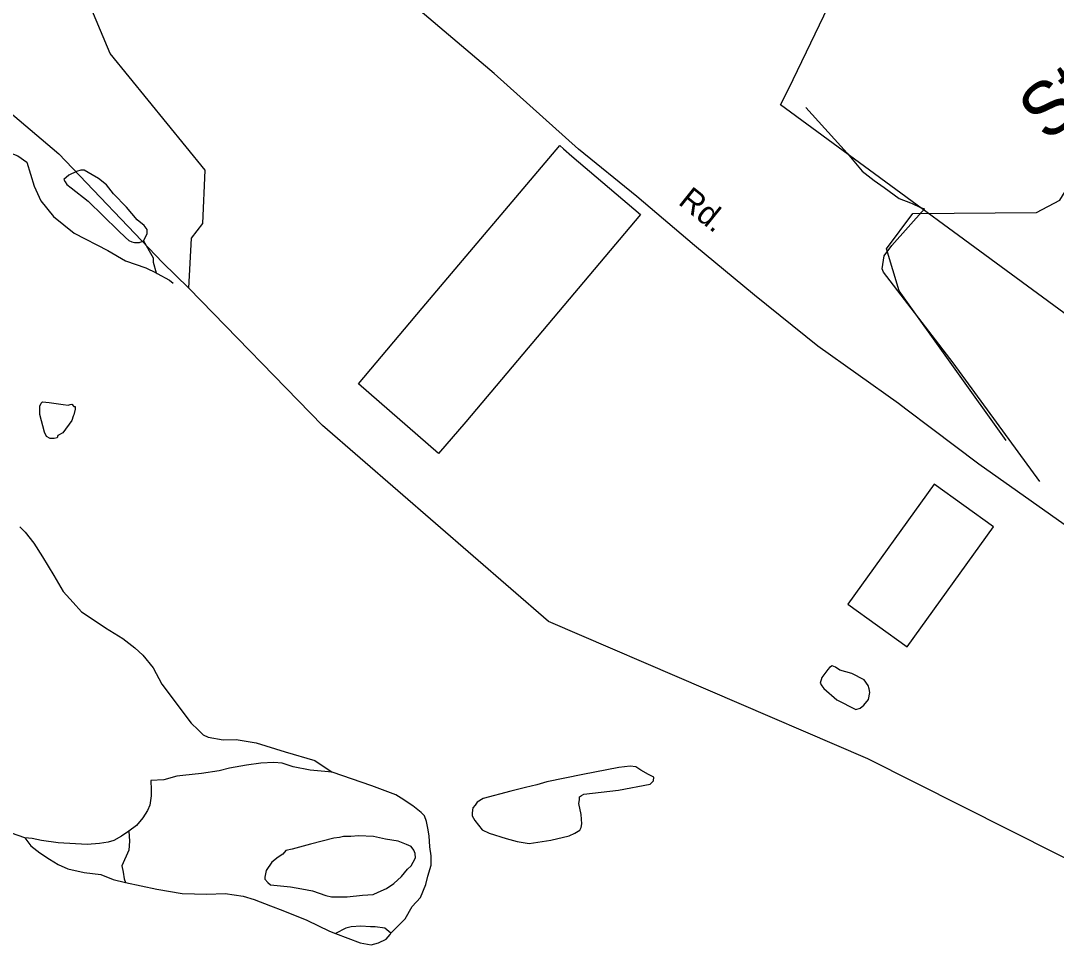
# Model space of a CAD drawing. Extents: x 2260773 to 2342389, y 552869 to 618546.
# Drawn here: x 2294422 to 2297350, y 579715 to 582357 of the extents above; entities that cross this region are included whole.
import ezdxf

# ---------------------------------------------------------------- set-up
doc = ezdxf.new("R2010")
doc.units = 0
for name, color, linetype in [('Exist Boundary Political City Limit New', 7, 'Continuous'), ('Exist Cultural Warehouse Building Footprint', 7, 'Continuous'), ('Exist Hydrographic Creek Single Shore', 7, 'Continuous'), ('Exist Hydrographic Creek Single Shore Label', 7, 'Continuous'), ('Exist Hydrographic Misc Water Feature', 7, 'Continuous'), ('Exist Road Non-System Type 51', 7, 'Continuous'), ('Exist Road Primary NC Attributed', 7, 'Continuous'), ('Exist Road Primary NC Label', 7, 'Continuous'), ('Map Preparation Boundary City Limit Buffer Line', 7, 'Continuous')]:
    doc.layers.add(name, color=color, linetype=linetype)

msp = doc.modelspace()

# ---------------------------------------------------------------- linework, layer by layer
at = {"layer": 'Exist Boundary Political City Limit New'}
for points in [[(2297445.2, 581475.9), (2296570.5, 582118.3), (2296593.2, 582165.2), (2296754.5, 582500), (2296819.2, 582635.4), (2297370.2, 583786.4)], [(2295681, 581222.9), (2295603, 581133.6), (2295377, 581330.5), (2295557.5, 581544), (2295946.2, 582003.4), (2295957, 581994.2), (2295980.5, 581974.1), (2296174.5, 581808.7), (2295681, 581222.9)]]:
    msp.add_lwpolyline(points, dxfattribs=at)
at = {"layer": 'Exist Cultural Warehouse Building Footprint'}
for p, q in [((2297004.7, 581046.7), (2296760.4, 580707.1)), ((2297172.5, 580925.9), (2297004.7, 581046.7)), ((2296928.2, 580586.4), (2297172.5, 580925.9)), ((2296760.4, 580707.1), (2296928.2, 580586.4))]:
    msp.add_line(p, q, dxfattribs=at)
at = {"layer": 'Exist Hydrographic Creek Single Shore'}
for points in [[(2292969.9, 583667.9), (2292987.1, 583615.9), (2293001.1, 583569.4), (2293015.1, 583532.6), (2293034.4, 583499.3), (2293058.5, 583475.8), (2293231.8, 583381.5), (2293333.8, 583298.8), (2293598.6, 582913), (2293764.8, 582672.6), (2293929.2, 582502.7), (2294211.5, 582249.8), (2294530.6, 581980.7), (2294822.8, 581672.8), (2294898, 581600.6)], [(2294898, 581600.6), (2294905, 581741.5), (2294937, 581783.4), (2294943.9, 581934.1), (2294674.9, 582264.3), (2294581, 582489.2)], [(2297207.9, 581170.1), (2296905.1, 581592.8), (2296870, 581711.5), (2296944, 581811.7), (2297294, 581814.4), (2297359.9, 581849.2), (2297482.9, 582050), (2297673, 582210.1), (2298113, 582404.6), (2298279.9, 582371.7)], [(2298305, 579714.8), (2297796, 579803.8), (2297620.1, 579866.4), (2296816.9, 580269.7), (2295914, 580658.5), (2295275.9, 581212.5), (2294898, 581600.6)]]:
    msp.add_lwpolyline(points, dxfattribs=at)
at = {"layer": 'Exist Hydrographic Misc Water Feature'}
for points in [[(2293992.5, 582136.5), (2293996.4, 582134.3), (2294414.1, 581974.5), (2294439.9, 581956.8), (2294460.4, 581888.8), (2294479.1, 581847.1), (2294515.2, 581803.5), (2294574, 581756.1), (2294668.4, 581707), (2294718.2, 581677.6), (2294776.6, 581657.9), (2294804.9, 581644.3)], [(2296641.4, 582111), (2296758.4, 581982.3), (2296800.9, 581930.9), (2296835.3, 581905.1), (2296863, 581885.4), (2296905.9, 581853.8), (2296937.9, 581842.2), (2296941.8, 581840.3), (2296965.8, 581828.2), (2296977.4, 581824.4)], [(2294769.6, 581733.9), (2294779.9, 581753.9), (2294779.9, 581762), (2294779.7, 581766.1), (2294771.5, 581777.9), (2294751.6, 581793.5), (2294721.3, 581829.2), (2294684.8, 581866.8), (2294664.5, 581893), (2294642.7, 581910.4), (2294624.3, 581920.5), (2294601.9, 581934.4), (2294592.3, 581934.2), (2294580, 581930), (2294558.4, 581919.9), (2294544.5, 581907.8), (2294548.4, 581901.5), (2294552.7, 581893.6), (2294564.8, 581884), (2294612.8, 581846.4), (2294697.7, 581763.1), (2294718.2, 581743.3), (2294727.8, 581735.4), (2294736.2, 581731.7), (2294743.8, 581729.7), (2294758, 581729.6), (2294769.6, 581733.9)], [(2297303.1, 581053.9), (2297058, 581389.3), (2296861.4, 581645.6), (2296857.5, 581655.6), (2296859.5, 581667.4), (2296863, 581691.6), (2296885.2, 581721.5), (2296977.4, 581824.4)], [(2294769.6, 581733.9), (2294796.5, 581686.1), (2294796.7, 581673.9), (2294804.9, 581644.3)], [(2294804.9, 581644.3), (2294808.4, 581642.1), (2294843.1, 581622.7), (2294853.1, 581614.8)], [(2294567.1, 581226.3), (2294541.4, 581192.1), (2294527.3, 581184), (2294525.4, 581177.8), (2294517.4, 581175.8), (2294509.2, 581175.8), (2294505.5, 581175.6), (2294495.1, 581181.6), (2294489.3, 581193.4), (2294476.8, 581243.6), (2294476.4, 581267.1), (2294480.5, 581275.5), (2294484.4, 581279.3), (2294502.5, 581277.4), (2294542.2, 581271.8), (2294556.4, 581270.1), (2294562.3, 581272.1), (2294566.6, 581272.2), (2294572.4, 581266.5), (2294576.7, 581266.3), (2294576.5, 581258.2), (2294572.6, 581242.1), (2294570.7, 581238.3), (2294567.1, 581226.3)], [(2296686.5, 580500.4), (2296682.2, 580484.5), (2296686.7, 580476.5), (2296692.6, 580468.7), (2296729.1, 580436.8), (2296783.3, 580409.6), (2296795.4, 580413.5), (2296805.2, 580421.7), (2296818.9, 580437.9), (2296822.6, 580458), (2296821, 580468), (2296818.3, 580477.7), (2296806.4, 580493.7), (2296772, 580511.4), (2296737.9, 580521.1), (2296726, 580528.9), (2296716.2, 580532.8), (2296708.2, 580528.7), (2296704.3, 580522.9), (2296686.5, 580500.4)], [(2295808, 580178.5), (2295730.1, 580157.8), (2295712.3, 580147.5), (2295706.7, 580139.5), (2295700.2, 580131.5), (2295698.7, 580117.5), (2295698.7, 580109.4), (2295706.5, 580095.6), (2295727, 580069.9), (2295746.9, 580059.9), (2295795.1, 580044.6), (2295825.3, 580036.8), (2295859.5, 580030.9), (2295921.2, 580039.8), (2295973.1, 580052.3), (2295988.9, 580060.5), (2296003, 580068.5), (2296006.9, 580076.4), (2296009, 580086.2), (2296006.5, 580112.5), (2296000.4, 580144.3), (2296002, 580154.2), (2296002, 580162.3), (2296007.8, 580166.3), (2296013.9, 580170.2), (2296111.9, 580181.4), (2296201.5, 580198.4), (2296207.5, 580204.3), (2296211.2, 580208.2), (2296211.6, 580218.3), (2296197.2, 580226.1), (2296175.3, 580238), (2296161.1, 580247.8), (2296144.9, 580249.4), (2296113.1, 580245.3), (2296011.4, 580226.1), (2295909.7, 580205.4), (2295881.6, 580197), (2295849.7, 580188.9), (2295808, 580178.5)], [(2295307.3, 580045.9), (2295241.7, 580029.4), (2295190, 580014.9), (2295171.8, 580010.7), (2295163.8, 580000.6), (2295150, 579992.5), (2295132, 579978.2), (2295116.6, 579954.2), (2295112.7, 579936.1), (2295112.5, 579930), (2295120.7, 579920.3), (2295128.9, 579914.2), (2295185.1, 579908.6), (2295216.9, 579903), (2295246.8, 579897.2), (2295284.9, 579883.8), (2295300.9, 579879.8), (2295345.2, 579880.4), (2295388.9, 579884.8), (2295419, 579887.1), (2295433.2, 579893.1), (2295456.6, 579903.4), (2295476.7, 579917.4), (2295498.4, 579937.6), (2295516.2, 579958), (2295526.3, 579967.9), (2295531.8, 579978), (2295538.2, 579990), (2295537.6, 580002.3), (2295533.7, 580012.2), (2295525.7, 580021.9), (2295513.4, 580027.8), (2295489.6, 580037.5), (2295453.5, 580043.3), (2295419.5, 580050.9), (2295377.2, 580052.4), (2295355.7, 580050.4), (2295335.2, 580050.2), (2295323.3, 580047.9), (2295307.3, 580045.9)]]:
    msp.add_lwpolyline(points, dxfattribs=at)
at = {"layer": 'Exist Road Non-System Type 51'}
for points in [[(2294419.8, 580926.1), (2294435.2, 580910.7), (2294459.7, 580879.7), (2294484.2, 580841), (2294516.5, 580788.1), (2294542.3, 580742.9), (2294570.7, 580711.9), (2294593.9, 580686.1), (2294618.4, 580669.3), (2294662.2, 580640.9), (2294711.2, 580610), (2294744.8, 580584.2), (2294768, 580563.5), (2294796.4, 580527.4), (2294820.9, 580480.9), (2294904.7, 580371.2), (2294924.1, 580351.9), (2294938.3, 580337.7), (2294952.4, 580331.2), (2294995, 580323.5), (2295031.1, 580324.8), (2295087.9, 580315.7), (2295170.4, 580289.9), (2295254.3, 580265.4), (2295302.6, 580232.5)], [(2295302.6, 580232.5), (2295240.7, 580238.3), (2295192.3, 580248), (2295161.4, 580257.7), (2295138.2, 580259.6), (2295101.4, 580257.7), (2295060.8, 580251.9), (2295012.4, 580244.1), (2294983.4, 580236.4), (2294933.1, 580228.6), (2294880.9, 580222.8), (2294863.4, 580220.9), (2294826.7, 580211.2), (2294789.9, 580209.3), (2294791.2, 580182.2), (2294791.2, 580165.4), (2294787.3, 580139.6), (2294780.9, 580124.1), (2294768, 580103.5), (2294749.9, 580081.5), (2294728, 580066)], [(2295469, 579777.6), (2295509.6, 579818.3), (2295529, 579853.1), (2295552.2, 579878.3), (2295567.7, 579915), (2295573.5, 579938.3), (2295583.1, 579969.2), (2295583.1, 579996.3), (2295579.3, 580021.5), (2295577.3, 580052.5), (2295573.5, 580073.8), (2295569.6, 580093.1), (2295563.8, 580108.6), (2295554.1, 580118.3), (2295530.9, 580137.7), (2295498, 580158.9), (2295482.5, 580168.6), (2295414.8, 580193.8), (2295302.6, 580232.5)], [(2294433.9, 580047.3), (2294396.5, 580059.6)], [(2294728, 580066), (2294707.4, 580051.2), (2294685.4, 580039.6), (2294670, 580034.4), (2294645.5, 580030.5), (2294610.6, 580028), (2294528.1, 580033.1), (2294481.7, 580039.6), (2294454.6, 580044.7), (2294433.9, 580047.3)], [(2294433.9, 580047.3), (2294450.7, 580024.1), (2294476.5, 580004.7), (2294503.6, 579986.7), (2294528.1, 579971.2), (2294555.2, 579959.6), (2294601.6, 579949.2), (2294649.3, 579942.8), (2294684.2, 579928.6), (2294718.3, 579920.8)], [(2294728, 580066), (2294729.9, 580037), (2294728, 580011.8), (2294708.7, 579967.3), (2294712.5, 579949.9), (2294714.5, 579930.5), (2294718.3, 579920.8)], [(2294718.3, 579920.8), (2294807.3, 579901.5), (2294878.9, 579889.9), (2294948.6, 579887.9), (2295000.8, 579889.9), (2295051.1, 579882.1), (2295082.1, 579872.5), (2295128.5, 579855), (2295163.3, 579841.5), (2295231, 579814.4), (2295295.4, 579782.7), (2295312.6, 579776.4)], [(2295469, 579777.6), (2295451.6, 579791.2), (2295424.5, 579795), (2295411, 579795), (2295383.9, 579797), (2295356.8, 579795), (2295341.3, 579791.2), (2295312.6, 579776.4)], [(2295312.6, 579776.4), (2295381.9, 579750.5), (2295412.9, 579744.7), (2295434.2, 579750.5), (2295455.5, 579760.2), (2295467.1, 579773.7), (2295469, 579777.6)]]:
    msp.add_lwpolyline(points, dxfattribs=at)
at = {"layer": 'Exist Road Primary NC Attributed'}
msp.add_lwpolyline([(2297777.1, 580639), (2297388.1, 580921.3), (2297130.7, 581102.6), (2296997, 581203.7), (2296924.6, 581258.4), (2296903.2, 581274.5), (2296675.8, 581436.3), (2296496.6, 581580.4), (2296327.3, 581720.8), (2296164.2, 581859.3), (2295998.9, 581993.6), (2295761, 582207.3), (2295109.1, 582760.6)], dxfattribs=at)
at = {"layer": 'Map Preparation Boundary City Limit Buffer Line'}
for points in [[(2297445.2, 581475.9), (2296570.5, 582118.3), (2296593.2, 582165.2), (2296754.5, 582500), (2296819.2, 582635.4), (2297370.2, 583786.4)], [(2295681, 581222.9), (2295603, 581133.6), (2295377, 581330.5), (2295557.5, 581544), (2295946.2, 582003.4), (2295957, 581994.2), (2295980.5, 581974.1), (2296174.5, 581808.7), (2295681, 581222.9)]]:
    msp.add_lwpolyline(points, dxfattribs=at)

# ---------------------------------------------------------------- texts
at = {"layer": 'Exist Hydrographic Creek Single Shore Label'}
msp.add_text('Stony', height=150, rotation=40.1142, dxfattribs=at).set_placement((2297324.2, 582010.6))
at = {"layer": 'Exist Road Primary NC Label'}
msp.add_text('Rd.', height=65.62, rotation=321.1959, dxfattribs=at).set_placement((2296278.1, 581840))

doc.saveas('drawing.dxf')
